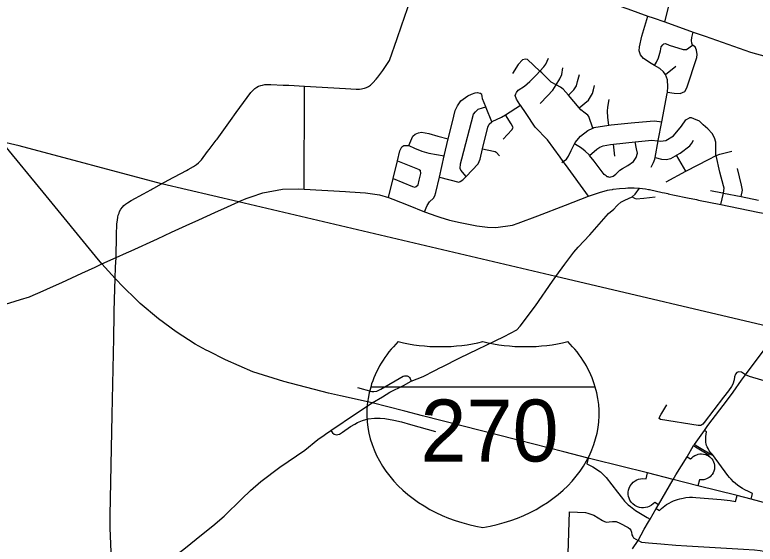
# Model space of a CAD drawing. Extents: x 1755200 to 1902939, y 644115 to 788070.
# Drawn here: x 1796306 to 1808258, y 692927 to 701476 of the extents above; entities that cross this region are included whole.
import ezdxf

# ---------------------------------------------------------------- set-up
doc = ezdxf.new("R2010")
doc.units = 0
for name, color, linetype in [('GM_X_City_Street', 7, 'Continuous'), ('GM_X_County_Road', 7, 'Continuous'), ('GM_X_Interchange_Ramps', 7, 'Continuous'), ('GM_X_Interstate_Route', 7, 'Continuous'), ('GM_X_Interstate_Shield', 7, 'Continuous'), ('GM_X_Township', 7, 'Continuous'), ('GM_X_Township_Road', 7, 'Continuous'), ('GM_X_US_Route', 7, 'Continuous')]:
    doc.layers.add(name, color=color, linetype=linetype)

msp = doc.modelspace()

# ---------------------------------------------------------------- linework, layer by layer
at = {"layer": 'GM_X_City_Street'}
for points in [[(1806800, 701361), (1807043, 702333)], [(1806577, 699015), (1806619, 699092), (1806638, 699144), (1806643, 699171), (1806692, 699439), (1806694, 699446), (1806751, 699746), (1806839, 700204), (1806841, 700225), (1806850, 700314), (1806844, 700425), (1806808, 700511), (1806806, 700518), (1806780, 700553), (1806719, 700606), (1806635, 700657), (1806580, 700691), (1806454, 700770), (1806405, 700829), (1806388, 700892), (1806393, 700958), (1806431, 701130), (1806461, 701238), (1806524, 701455)], [(1806610, 701426), (1806800, 701361), (1807256, 701197), (1807451, 701129)], [(1806841, 700225), (1806953, 700208), (1807047, 700203), (1807120, 700235), (1807154, 700295), (1807316, 700784), (1807320, 700834), (1807310, 700902), (1807287, 700956), (1807247, 700983), (1807233, 701020), (1807228, 701063), (1807233, 701111), (1807256, 701197)], [(1806635, 700657), (1806664, 700713), (1806696, 700780), (1806729, 700894), (1806743, 700958), (1806765, 700993), (1806783, 701009), (1806813, 701011), (1806869, 700985), (1807095, 700914), (1807149, 700914), (1807247, 700983)], [(1804812, 700538), (1804783, 700565), (1804581, 700756), (1804550, 700758), (1804500, 700749), (1804434, 700671), (1804338, 700528)], [(1804783, 700565), (1804844, 700634), (1804876, 700676), (1804924, 700777)], [(1804396, 700201), (1804406, 700219), (1804430, 700257), (1804532, 700322), (1804622, 700399), (1804726, 700505), (1804783, 700565)], [(1805046, 700344), (1805106, 700440), (1805138, 700511), (1805154, 700619)], [(1806808, 700511), (1806975, 700646)], [(1805635, 699645), (1805571, 699832), (1805556, 699854), (1805512, 699886), (1805446, 699942), (1805419, 699972), (1805242, 700176), (1805157, 700274), (1805113, 700306), (1805046, 700344), (1804964, 700390), (1804851, 700502), (1804813, 700538), (1804812, 700538)], [(1805242, 700176), (1805330, 700263), (1805372, 700329), (1805392, 700397), (1805423, 700514)], [(1799787, 699770), (1799879, 699896), (1800117, 700220), (1800153, 700261), (1800183, 700286), (1800212, 700307), (1800242, 700323), (1800278, 700336), (1800303, 700342), (1800343, 700349), (1800389, 700352), (1800440, 700351), (1800639, 700341), (1800730, 700337)], [(1804786, 700046), (1804906, 700165), (1804992, 700257), (1805046, 700344)], [(1805419, 699972), (1805565, 700099), (1805601, 700149), (1805633, 700206), (1805647, 700266), (1805665, 700332)], [(1803619, 700168), (1803679, 700194), (1803739, 700217), (1803777, 700219), (1803811, 700209)], [(1804005, 699747), (1803915, 699972), (1803908, 699991), (1803858, 700121), (1803852, 700161), (1803846, 700191), (1803811, 700209)], [(1804708, 699662), (1804562, 699882), (1804468, 700014), (1804459, 700027), (1804406, 700113), (1804386, 700171), (1804396, 700201)], [(1802919, 698295), (1802964, 698395), (1803001, 698454), (1803063, 698513), (1803088, 698554), (1803102, 698605), (1803160, 698854), (1803235, 699196), (1803303, 699473), (1803371, 699749), (1803417, 699930), (1803451, 700005), (1803507, 700089), (1803619, 700168)], [(1805898, 699693), (1805880, 699815), (1805872, 699917), (1805877, 699984), (1805903, 700106)], [(1803472, 698772), (1803494, 698782), (1803538, 698809), (1803593, 698866), (1803788, 699071), (1803818, 699145), (1803857, 699309), (1803940, 699659), (1803966, 699710), (1804005, 699747), (1804012, 699754), (1804163, 699821), (1804230, 699863), (1804468, 700014)], [(1803593, 698866), (1803507, 698967), (1803497, 698995), (1803501, 699067), (1803523, 699152), (1803710, 699869), (1803742, 699911), (1803788, 699954), (1803855, 699976), (1803908, 699991)], [(1804188, 699469), (1804260, 699542), (1804332, 699617), (1804350, 699657), (1804320, 699715), (1804230, 699863)], [(1805135, 699089), (1805159, 699106), (1805212, 699143), (1805243, 699191), (1805289, 699284), (1805342, 699393), (1805352, 699414), (1805440, 699516), (1805558, 699608), (1805635, 699645), (1805655, 699654), (1805898, 699693), (1805931, 699699), (1806256, 699730), (1806562, 699760), (1806632, 699761), (1806751, 699746)], [(1805586, 699203), (1805701, 699308), (1805749, 699339), (1805806, 699360), (1805921, 699380), (1805973, 699385), (1806322, 699422), (1806592, 699450), (1806680, 699441), (1806692, 699439), (1806732, 699433), (1806816, 699448), (1806942, 699519), (1807071, 699679), (1807140, 699782), (1807200, 699811)], [(1807705, 698411), (1807745, 698595), (1807756, 698677), (1807749, 698714), (1807690, 698934), (1807627, 699202), (1807625, 699208), (1807623, 699283), (1807622, 699367), (1807624, 699419), (1807603, 699488), (1807562, 699557), (1807492, 699637), (1807421, 699698), (1807358, 699756), (1807268, 699794), (1807230, 699811), (1807200, 699811)], [(1805108, 699176), (1804907, 699455), (1804708, 699662)], [(1802666, 699365), (1802734, 699518), (1802768, 699546), (1802824, 699569), (1802870, 699581), (1802989, 699557), (1803135, 699516), (1803303, 699473), (1803308, 699472)], [(1799445, 699301), (1799557, 699451), (1799571, 699470)], [(1802338, 698525), (1802412, 698832), (1802482, 699118), (1802522, 699279), (1802552, 699343), (1802588, 699367), (1802620, 699367), (1802666, 699365)], [(1802666, 699365), (1802759, 699324), (1802879, 699272), (1802992, 699240), (1803235, 699196), (1803244, 699194)], [(1805890, 698858), (1805870, 698861), (1805850, 698873), (1805823, 698896), (1805770, 698963), (1805661, 699110), (1805586, 699203), (1805576, 699214), (1805515, 699274), (1805454, 699323), (1805342, 699393)], [(1805890, 698858), (1805912, 698856), (1805966, 698869), (1806007, 698904), (1806075, 698967), (1806115, 698994), (1806205, 699043), (1806292, 699105), (1806337, 699173), (1806361, 699240), (1806344, 699311), (1806322, 699422)], [(1805993, 699194), (1805973, 699385)], [(1806970, 699199), (1806972, 699200), (1806986, 699208), (1807049, 699244), (1807201, 699362), (1807234, 699403), (1807265, 699453)], [(1803857, 699309), (1804034, 699276), (1804060, 699266), (1804077, 699260), (1804129, 699198)], [(1807626, 699202), (1807627, 699202), (1807631, 699204), (1807690, 699223), (1807883, 699275)], [(1802482, 699118), (1802836, 698977), (1802855, 698959)], [(1806643, 699171), (1806748, 699142), (1806822, 699140), (1806894, 699155), (1806970, 699199)], [(1807140, 698949), (1806986, 699208)], [(1807151, 698955), (1807152, 698955), (1807504, 699139), (1807626, 699202)], [(1808030, 698543), (1808051, 698644), (1808048, 698670), (1808039, 698726), (1807974, 698996)], [(1798780, 698803), (1799076, 698964), (1799104, 698980)], [(1802783, 698701), (1802815, 698730), (1802835, 698806), (1802863, 698915), (1802855, 698959)], [(1806819, 698781), (1807140, 698949), (1807151, 698955)], [(1798548, 698676), (1798676, 698746), (1798780, 698803)], [(1802412, 698832), (1802725, 698701), (1802763, 698695), (1802783, 698701)], [(1803160, 698854), (1803472, 698772)], [(1798502, 698651), (1798517, 698659), (1798548, 698676)], [(1805904, 698647), (1805957, 698657)], [(1806536, 698655), (1806554, 698652), (1806759, 698606), (1806794, 698599)], [(1807535, 698641), (1807729, 698599)], [(1801644, 698622), (1801713, 698618), (1801966, 698600), (1802191, 698566), (1802338, 698525), (1802410, 698501), (1802654, 698404), (1802919, 698295), (1803119, 698224)], [(1806846, 698589), (1806856, 698586), (1806957, 698564), (1807168, 698522), (1807312, 698491)], [(1807729, 698599), (1807745, 698595), (1808030, 698543), (1808311, 698481)], [(1807312, 698491), (1807342, 698485), (1807705, 698411), (1808302, 698291), (1808557, 698239)], [(1796541, 696924), (1796553, 696928), (1796764, 697018), (1796881, 697072)], [(1794815, 696413), (1794824, 696413), (1794882, 696423), (1795150, 696503), (1795462, 696597), (1795846, 696710), (1796227, 696823), (1796396, 696877), (1796541, 696924)], [(1797905, 696254), (1797907, 696375), (1797908, 696515)], [(1803086, 695733), (1803180, 695780)], [(1801837, 695457), (1802071, 695392), (1802100, 695393), (1802152, 695400), (1802217, 695432), (1802573, 695638), (1802597, 695644), (1802616, 695647), (1802639, 695647), (1802664, 695635), (1802678, 695620), (1802691, 695600), (1802703, 695558)], [(1802240, 695309), (1802361, 695381), (1802580, 695491), (1802703, 695558), (1802896, 695637), (1803086, 695733)], [(1808072, 695681), (1808037, 695704), (1807997, 695711), (1807963, 695701), (1807941, 695673), (1807925, 695628), (1807918, 695580), (1807899, 695512), (1807877, 695473), (1807825, 695401), (1807748, 695302)], [(1806750, 695042), (1806832, 695177)], [(1801406, 694763), (1801437, 694726), (1801463, 694706), (1801497, 694694), (1801519, 694696), (1801547, 694706), (1801597, 694738), (1801724, 694826), (1801794, 694866), (1801839, 694892), (1801921, 694926), (1802009, 694950), (1802110, 694964), (1802206, 694963), (1802280, 694955), (1802425, 694929), (1802551, 694904), (1802693, 694862), (1803096, 694748)], [(1798053, 692007), (1797971, 692192), (1797941, 692271), (1797917, 692355), (1797904, 692401), (1797884, 692501), (1797878, 692547), (1797873, 692618), (1797868, 692670), (1797847, 693189), (1797846, 693385)], [(1805026, 692311), (1805038, 692331), (1805045, 692340), (1805064, 692370), (1805216, 692614), (1805227, 692652), (1805238, 692774), (1805259, 693450)], [(1805259, 693450), (1805517, 693438), (1805555, 693426), (1805655, 693397), (1805795, 693308)], [(1805795, 693308), (1805827, 693292), (1805856, 693283), (1805899, 693288), (1805957, 693296), (1806012, 693296), (1806072, 693267), (1806208, 693197), (1806235, 693177), (1806250, 693155), (1806259, 693123), (1806269, 693080), (1806282, 693053), (1806295, 693031), (1806367, 692985)], [(1808561, 692742), (1808500, 692775), (1808442, 692798), (1808400, 692809), (1808340, 692819), (1808246, 692828), (1808072, 692839), (1807153, 692896), (1806977, 692908), (1806733, 692925), (1806538, 692944), (1806430, 692955), (1806367, 692985)]]:
    msp.add_lwpolyline(points, dxfattribs=at)
at = {"layer": 'GM_X_County_Road'}
for points in [[(1803315, 702487), (1803764, 702341), (1804096, 702233), (1805139, 701916), (1805577, 701784), (1805891, 701680), (1806203, 701571), (1806524, 701455), (1806610, 701426)], [(1802480, 701095), (1802551, 701300), (1802692, 701723), (1802797, 702012), (1802808, 702043)], [(1800730, 700337), (1800984, 700323), (1801646, 700286), (1801814, 700276), (1801871, 700273), (1801902, 700278), (1801923, 700283), (1801953, 700289), (1801982, 700300), (1802015, 700317), (1802050, 700342), (1802085, 700376), (1802140, 700435), (1802166, 700469), (1802249, 700577), (1802356, 700738), (1802480, 701095)], [(1807451, 701129), (1808185, 700873), (1808437, 700800), (1808633, 700748), (1808853, 700693)], [(1799571, 699470), (1799733, 699696), (1799787, 699770)], [(1799104, 698980), (1799188, 699026), (1799239, 699061), (1799269, 699084), (1799321, 699135), (1799419, 699266), (1799445, 699301)], [(1797932, 697401), (1797940, 697557), (1797947, 697919), (1797955, 698101), (1797962, 698160), (1797969, 698208), (1797977, 698241), (1797988, 698274), (1797998, 698299), (1798016, 698336), (1798042, 698371), (1798066, 698397), (1798093, 698418), (1798125, 698440), (1798184, 698477), (1798381, 698584), (1798502, 698651)], [(1800121, 698536), (1800311, 698601), (1800627, 698662), (1800890, 698665), (1800976, 698662), (1801644, 698622)], [(1803119, 698224), (1803167, 698207), (1803325, 698162), (1803496, 698122), (1803762, 698070), (1803935, 698045), (1804070, 698041), (1804343, 698079), (1804431, 698109), (1804747, 698228), (1805198, 698401), (1805443, 698499), (1805566, 698549), (1805747, 698604), (1805876, 698642), (1805904, 698647)], [(1805957, 698657), (1805964, 698658), (1806067, 698672), (1806167, 698678)], [(1806025, 698390), (1806040, 698406), (1806092, 698448), (1806155, 698484), (1806271, 698538), (1806319, 698579), (1806392, 698676)], [(1806167, 698678), (1806200, 698680), (1806303, 698683), (1806392, 698676), (1806487, 698664), (1806536, 698655)], [(1798183, 697665), (1798609, 697859), (1798838, 697964), (1799073, 698071), (1799278, 698165), (1799534, 698282), (1799741, 698377), (1799916, 698454), (1799940, 698465), (1800040, 698508), (1800121, 698536)], [(1806794, 698599), (1806846, 698589)], [(1805217, 697491), (1805328, 697643), (1805399, 697725), (1805587, 697924), (1805890, 698265), (1805977, 698337), (1806025, 698390)], [(1797603, 697403), (1797710, 697452), (1797940, 697557), (1798111, 697632), (1798183, 697665)], [(1803180, 695780), (1803196, 695788), (1803205, 695793), (1803489, 695935), (1804208, 696280), (1804409, 696389), (1804466, 696449), (1804713, 696775), (1804984, 697173), (1805040, 697248), (1805185, 697448), (1805217, 697491)], [(1796881, 697072), (1797064, 697155), (1797387, 697304), (1797603, 697403)], [(1797915, 696880), (1797924, 697218), (1797932, 697401)], [(1797908, 696515), (1797909, 696679), (1797915, 696880)], [(1797846, 693385), (1797846, 693388), (1797880, 695015), (1797905, 696254)], [(1801319, 694702), (1801406, 694763), (1801409, 694764), (1801822, 695042), (1802076, 695212), (1802240, 695309)], [(1798626, 692522), (1798701, 692591), (1799037, 692849), (1799349, 693097), (1799503, 693222), (1799684, 693381), (1799969, 693662), (1800112, 693793), (1800279, 693941), (1800585, 694169), (1800986, 694447), (1801200, 694620), (1801300, 694689), (1801319, 694702)]]:
    msp.add_lwpolyline(points, dxfattribs=at)
at = {"layer": 'GM_X_Interchange_Ramps'}
for points in [[(1808191, 693653), (1808215, 693744), (1808148, 693778), (1808093, 693804), (1808051, 693827), (1808010, 693853), (1807972, 693881), (1807939, 693907), (1807907, 693936), (1807868, 693975), (1807842, 694004), (1807817, 694035), (1807567, 694373), (1807545, 694403), (1807518, 694436), (1807497, 694471), (1807484, 694498), (1807475, 694523), (1807468, 694548), (1807463, 694570), (1807459, 694602), (1807459, 694632), (1807461, 694667), (1807474, 694739), (1807441, 694763)], [(1807264, 694519), (1807294, 694498), (1807512, 694368), (1807503, 694354)], [(1807567, 694373), (1807559, 694366), (1807306, 694517), (1807276, 694537)], [(1807159, 694338), (1807214, 694304), (1807234, 694323), (1807258, 694342), (1807284, 694358), (1807314, 694372), (1807340, 694380), (1807365, 694385), (1807394, 694386), (1807426, 694383), (1807458, 694375), (1807480, 694367), (1807503, 694354), (1807525, 694338), (1807544, 694321), (1807559, 694303), (1807572, 694284), (1807585, 694259), (1807595, 694229), (1807600, 694203), (1807602, 694165), (1807599, 694138), (1807590, 694106), (1807578, 694077), (1807564, 694054), (1807548, 694034), (1807531, 694017), (1807515, 694004), (1807495, 693992), (1807472, 693980), (1807447, 693971), (1807429, 693967), (1807406, 693964), (1807359, 693964), (1807335, 693869)], [(1805563, 694318), (1805538, 694223), (1805594, 694198), (1805639, 694175), (1805680, 694150), (1805717, 694125), (1805760, 694093), (1805787, 694068), (1805817, 694040), (1805850, 694005), (1806035, 693768), (1806116, 693663), (1806147, 693624), (1806177, 693593), (1806208, 693564), (1806244, 693534), (1806273, 693512), (1806328, 693472), (1806514, 693359), (1806564, 693330)], [(1806698, 693563), (1806637, 693599), (1806585, 693559), (1806547, 693536), (1806518, 693525), (1806487, 693517), (1806455, 693514), (1806422, 693515), (1806390, 693520), (1806358, 693530), (1806316, 693552), (1806285, 693577), (1806256, 693608), (1806236, 693640), (1806223, 693671), (1806215, 693699), (1806210, 693727), (1806210, 693768), (1806215, 693801), (1806225, 693834), (1806240, 693867), (1806266, 693904), (1806290, 693928), (1806320, 693951), (1806350, 693966), (1806377, 693976), (1806405, 693983), (1806435, 693986), (1806496, 693984), (1806522, 694078)], [(1806662, 693502), (1806711, 693473), (1806748, 693506), (1806775, 693527), (1806802, 693548), (1806829, 693566), (1806870, 693590), (1806907, 693610), (1806940, 693625), (1806972, 693637), (1807005, 693649), (1807042, 693660), (1807094, 693671), (1807140, 693679), (1807197, 693684), (1807248, 693685), (1807299, 693682), (1807707, 693646), (1807853, 693633), (1807941, 693616), (1807966, 693712)]]:
    msp.add_lwpolyline(points, dxfattribs=at)
at = {"layer": 'GM_X_Interstate_Route'}
for points in [[(1797609, 697576), (1796813, 698552), (1796095, 699426), (1795445, 700217), (1795043, 700707)], [(1798257, 696886), (1798060, 697077), (1797924, 697218), (1797710, 697452), (1797609, 697576)], [(1799397, 696062), (1799218, 696156), (1798912, 696355), (1798623, 696568), (1798331, 696814), (1798257, 696886)], [(1801565, 695324), (1801371, 695366), (1800650, 695552), (1800150, 695708), (1799705, 695904), (1799432, 696044), (1799397, 696062)], [(1802604, 695074), (1802580, 695081), (1802076, 695212), (1801565, 695324)], [(1804453, 694603), (1804346, 694630), (1804155, 694679), (1802887, 695001), (1802604, 695074)], [(1804665, 694548), (1804453, 694603)], [(1805650, 694296), (1805563, 694318), (1805170, 694418), (1804665, 694548)], [(1806933, 693974), (1806522, 694078), (1805650, 694296)], [(1814550, 691551), (1814371, 691658), (1813743, 692005), (1813454, 692129), (1812965, 692338), (1812503, 692508), (1811842, 692696), (1810502, 693057), (1810161, 693145), (1809234, 693383), (1808695, 693522), (1808191, 693653), (1807966, 693712), (1807335, 693869), (1806933, 693974)]]:
    msp.add_lwpolyline(points, dxfattribs=at)
at = {"layer": 'GM_X_Interstate_Shield'}
msp.add_line((1805677, 695465), (1802051, 695465), dxfattribs=at)
msp.add_line((1805677, 695465), (1802051, 695465), dxfattribs=at)
for centre, start_param, end_param in [((1804333, 695036), 2.47259, 2.911027), ((1803179, 697992), 4.415841, 5.008937), ((1804549, 697992), 4.415841, 5.008937), ((1803395, 695036), 0.230566, 0.669003), ((1804333, 695036), 2.911027, 4.511031), ((1803395, 695036), 4.913747, 6.513751)]:
    msp.add_ellipse(centre, major_axis=(2344, 0), ratio=0.8, start_param=start_param, end_param=end_param, dxfattribs=at)
at = {"layer": 'GM_X_Township'}
msp.add_lwpolyline([(1820279, 693511), (1817907, 694087), (1815708, 694629), (1815087, 694884), (1813506, 695256), (1811163, 695807), (1810869, 695876), (1810570, 695947), (1810511, 695961), (1809948, 696080), (1809281, 696250), (1808653, 696398), (1805040, 697248), (1799916, 698454), (1798676, 698746), (1796374, 699359), (1796095, 699426)], dxfattribs=at)
at = {"layer": 'GM_X_Township_Road'}
for points in [[(1800976, 698662), (1800979, 699278), (1800983, 699633), (1800984, 700323)], [(1805194, 699058), (1805159, 699106), (1805156, 699109), (1805108, 699176)], [(1805566, 698549), (1805194, 699058)], [(1806271, 698538), (1806309, 698512), (1806339, 698505), (1806462, 698516), (1806643, 698537)], [(1809889, 693372), (1809930, 693564), (1810030, 693949), (1810122, 694338), (1810212, 694726), (1810283, 695008), (1810286, 695042), (1810282, 695069), (1810263, 695086), (1810215, 695100), (1809336, 695322), (1808368, 695573), (1808168, 695635), (1808102, 695662), (1808072, 695681)], [(1807748, 695302), (1807437, 694894), (1807412, 694866), (1807380, 694846), (1807340, 694843), (1806729, 694939), (1806708, 694958), (1806718, 694988), (1806742, 695028), (1806750, 695042)]]:
    msp.add_lwpolyline(points, dxfattribs=at)
at = {"layer": 'GM_X_US_Route'}
for points in [[(1808040, 695573), (1808102, 695662), (1808406, 696068)], [(1807809, 695257), (1807904, 695382), (1808040, 695573)], [(1806978, 694047), (1807159, 694338), (1807264, 694519), (1807276, 694537), (1807441, 694763), (1807494, 694846), (1807809, 695257)], [(1806538, 693288), (1806564, 693330), (1806662, 693502), (1806698, 693563), (1806933, 693974), (1806978, 694047)], [(1806278, 692854), (1806367, 692985), (1806464, 693168), (1806538, 693288)]]:
    msp.add_lwpolyline(points, dxfattribs=at)

# ---------------------------------------------------------------- texts
at = {"layer": 'GM_X_Interstate_Shield'}
msp.add_text('270', height=1000, dxfattribs=at).set_placement((1802854, 694262))

doc.saveas('drawing.dxf')
